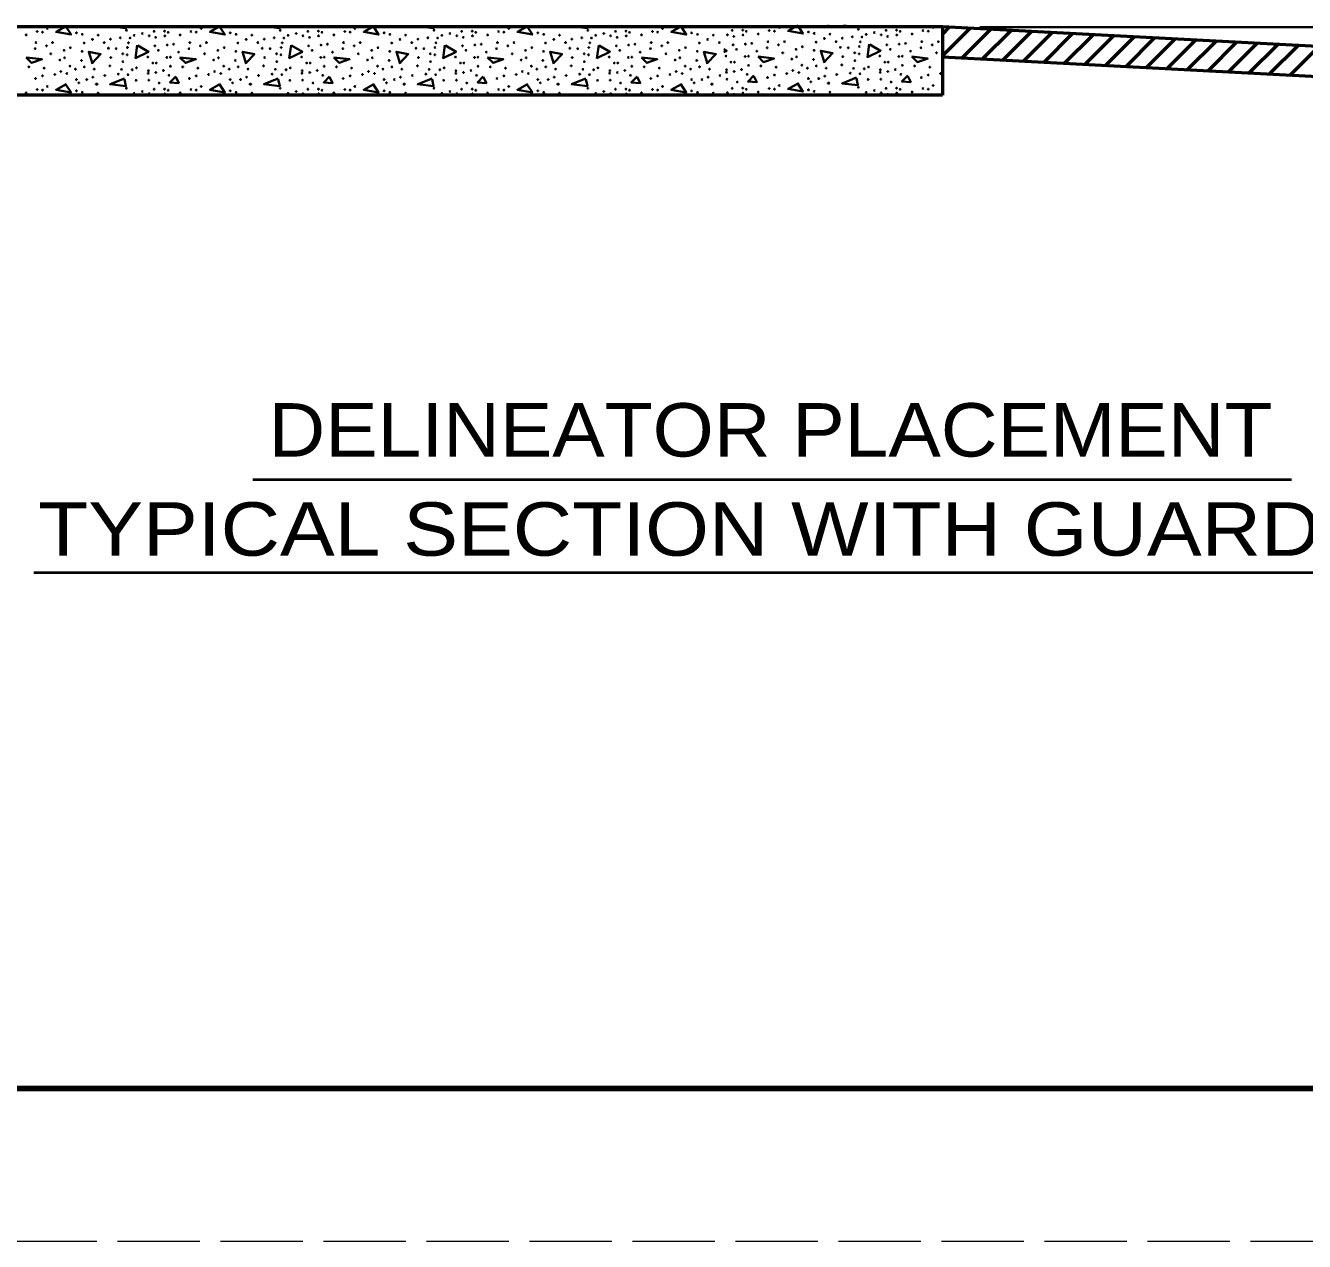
# Model space of a CAD drawing. Extents: x -54 to 626, y -41 to 399.
# Drawn here: x 33.7 to 117.5, y -41.3 to 38.4 of the extents above; entities that cross this region are included whole.
import ezdxf
from ezdxf.enums import TextEntityAlignment as Align

# ---------------------------------------------------------------- set-up
doc = ezdxf.new("R2010")
doc.units = 0
doc.header["$LTSCALE"] = 0.9
doc.linetypes.add('LONG_DASHED', pattern=[7.5, 6, -1.5])
doc.layers.add('1', color=7, linetype='Continuous', lineweight=35)
doc.layers.add('61', color=7, linetype='Continuous', lineweight=35)

msp = doc.modelspace()

# ---------------------------------------------------------------- linework, layer by layer
at = {"layer": '1', "lineweight": 53}
for p, q in [((93.8158, 38.3083), (140.6464, 35.8671)), ((93.8158, 37.7912), (94.3072, 38.2827)), ((93.8158, 36.377), (95.6514, 38.2126)), ((95.0863, 36.2332), (96.9956, 38.1425)), ((96.4301, 36.1628), (98.3397, 38.0724)), ((97.7739, 36.0924), (99.6838, 38.0024)), ((99.1177, 36.022), (101.028, 37.9323)), ((100.4615, 35.9516), (102.3722, 37.8622)), ((101.8053, 35.8812), (103.7163, 37.7922)), ((103.1491, 35.8107), (105.0604, 37.7221)), ((104.4928, 35.7403), (106.4046, 37.6521)), ((105.8366, 35.6699), (107.7488, 37.582)), ((107.1804, 35.5994), (109.0928, 37.5119)), ((108.5242, 35.529), (110.437, 37.4418)), ((109.868, 35.4586), (111.7812, 37.3717)), ((111.2117, 35.3882), (113.1253, 37.3017)), ((112.5556, 35.3177), (114.4694, 37.2317)), ((113.8993, 35.2473), (115.8136, 37.1616)), ((115.2432, 35.1769), (117.1577, 37.0915)), ((116.5869, 35.1065), (118.5019, 37.0214)), ((140.6464, 33.8456), (93.8156, 36.2998)), ((93.8158, 33.8083), (-1.1842, 33.8083))]:
    msp.add_line(p, q, dxfattribs=at)
at = {"layer": '1'}
msp.add_line((96.2767, 38.2649), (133.843, 38.2649), dxfattribs=at)
at = {"layer": '1', "lineweight": 40}
for p, q in [((48.6275, 8.6172), (116.6877, 8.6172)), ((34.2753, 2.5087), (131.065, 2.5087))]:
    msp.add_line(p, q, dxfattribs=at)
at = {"layer": '1', "lineweight": 53}
msp.add_lwpolyline([(-1.1842, 38.3083), (93.8158, 38.3083), (93.8158, 36.3054), (93.8158, 33.8083)], dxfattribs=at)
at = {"layer": '1'}
for points in [[(36.3717, 38.3083), (35.7318, 37.9592), (36.7118, 37.7792)], [(46.4517, 38.3083), (45.8118, 37.9592), (46.7918, 37.7792)], [(56.5317, 38.3083), (55.8918, 37.9592), (56.8718, 37.7792)], [(76.6917, 38.3083), (76.0518, 37.9592), (77.0318, 37.7792)], [(84.3422, 38.3702), (83.7023, 38.0212), (84.6823, 37.8412)], [(33.7718, 36.2792), (34.8118, 36.1593), (34.1318, 35.9192)], [(43.8518, 36.2792), (44.8918, 36.1593), (44.2118, 35.9192)], [(53.9318, 36.2792), (54.9718, 36.1593), (54.2918, 35.9192)], [(64.0118, 36.2792), (65.0518, 36.1593), (64.3718, 35.9192)], [(74.0918, 36.2792), (75.1318, 36.1593), (74.4518, 35.9192)], [(81.7423, 36.3412), (82.7823, 36.2212), (82.1023, 35.9812)], [(91.8223, 36.3412), (92.8623, 36.2212), (92.1823, 35.9812)]]:
    msp.add_lwpolyline(points, close=True, dxfattribs=at)
for points in [[(39.3672, 38.3083), (40.3118, 38.1992), (40.2882, 38.3083)], [(49.4472, 38.3083), (50.3918, 38.1992), (50.3682, 38.3083)], [(59.5272, 38.3083), (60.4718, 38.1992), (60.4482, 38.3083)], [(66.6117, 38.3083), (65.9718, 37.9592), (66.9518, 37.7792), (66.6118, 38.3083)], [(69.6072, 38.3083), (70.5518, 38.1992), (70.5282, 38.3083)], [(87.3377, 38.3702), (88.2823, 38.2612), (88.2587, 38.3702)], [(41.0918, 37.0592), (41.7918, 36.6593), (40.9318, 36.2392), (41.0518, 37.0793)], [(51.1718, 37.0592), (51.8718, 36.6593), (51.0118, 36.2392), (51.1318, 37.0793)], [(61.2518, 37.0592), (61.9518, 36.6593), (61.0918, 36.2392), (61.2118, 37.0793)], [(71.3318, 37.0592), (72.0318, 36.6593), (71.1718, 36.2392), (71.2918, 37.0793)], [(89.0623, 37.1212), (89.7623, 36.7212), (88.9023, 36.3012), (89.0223, 37.1412)], [(38.1118, 35.8592), (37.8718, 36.6593), (38.6518, 36.4992), (38.0918, 35.8993)], [(48.1918, 35.8592), (47.9518, 36.6593), (48.7318, 36.4992), (48.1718, 35.8993)], [(58.2718, 35.8592), (58.0318, 36.6593), (58.8118, 36.4992), (58.2518, 35.8993)], [(68.3518, 35.8592), (68.1118, 36.6593), (68.8918, 36.4992), (68.3318, 35.8993)], [(78.4318, 35.8592), (78.1918, 36.6593), (78.9718, 36.4992), (78.4118, 35.8993)], [(79.4887, 36.8318), (79.6823, 36.7212), (79.4887, 36.6266)], [(86.0823, 35.9212), (85.8423, 36.7212), (86.6223, 36.5612), (86.0623, 35.9612)], [(36.3918, 34.5192), (35.7318, 34.1593), (36.7118, 33.9793), (36.3518, 34.5392)], [(40.2118, 34.8993), (39.2718, 34.5192), (40.3118, 34.3993), (40.2118, 34.8592)], [(43.5718, 35.0392), (43.1918, 34.6392), (43.7718, 34.5992), (43.5718, 34.9992)], [(46.4718, 34.5192), (45.8118, 34.1593), (46.7918, 33.9793), (46.4318, 34.5392)], [(50.2918, 34.8993), (49.3518, 34.5192), (50.3918, 34.3993), (50.2918, 34.8592)], [(53.6518, 35.0392), (53.2718, 34.6392), (53.8518, 34.5992), (53.6518, 34.9992)], [(56.5518, 34.5192), (55.8918, 34.1593), (56.8718, 33.9793), (56.5118, 34.5392)], [(60.3718, 34.8993), (59.4318, 34.5192), (60.4718, 34.3993), (60.3718, 34.8592)], [(63.7318, 35.0392), (63.3518, 34.6392), (63.9318, 34.5992), (63.7318, 34.9992)], [(66.6318, 34.5192), (65.9718, 34.1593), (66.9518, 33.9793), (66.5918, 34.5392)], [(70.4518, 34.8993), (69.5118, 34.5192), (70.5518, 34.3993), (70.4518, 34.8592)], [(73.8118, 35.0392), (73.4318, 34.6392), (74.0118, 34.5992), (73.8118, 34.9992)], [(76.7118, 34.5192), (76.0518, 34.1593), (77.0318, 33.9793), (76.6718, 34.5392)], [(81.4623, 35.1012), (81.0823, 34.7012), (81.6623, 34.6612), (81.4623, 35.0612)], [(84.3623, 34.5812), (83.7023, 34.2212), (84.6823, 34.0412), (84.3223, 34.6012)], [(88.1823, 34.9612), (87.2423, 34.5812), (88.2823, 34.4612), (88.1823, 34.9212)], [(91.5423, 35.1012), (91.1623, 34.7012), (91.7423, 34.6612), (91.5423, 35.0612)]]:
    msp.add_lwpolyline(points, dxfattribs=at)
for centre in [(33.7796, 37.7563), (34.4953, 37.9817), (34.84, 37.942), (35.158, 38.1806), (37.0665, 37.8889), (37.4508, 37.7961), (38.4846, 37.743), (40.34, 38.0612), (40.8568, 37.7298), (41.3869, 37.8491), (41.8376, 37.7033), (42.1556, 37.995), (42.8448, 38.0082), (42.858, 37.69), (43.0778, 37.9287), (43.8596, 37.7563), (44.5753, 37.9817), (44.92, 37.942), (45.238, 38.1806), (47.1465, 37.8889), (47.5308, 37.7961), (48.5646, 37.743), (50.42, 38.0612), (50.9368, 37.7298), (51.4669, 37.8491), (51.9176, 37.7033), (52.2356, 37.995), (52.9248, 38.0082), (52.938, 37.69), (53.1578, 37.9287), (53.9396, 37.7563), (54.6553, 37.9817), (55, 37.942), (55.318, 38.1806), (57.2265, 37.8889), (57.6108, 37.7961), (58.6446, 37.743), (60.5, 38.0612), (61.0168, 37.7298), (61.5469, 37.8491), (61.9976, 37.7033), (62.3156, 37.995), (63.0048, 38.0082), (63.018, 37.69), (63.2378, 37.9287), (64.0196, 37.7563), (64.7353, 37.9817), (65.08, 37.942), (65.398, 38.1806), (67.3065, 37.8889), (67.6908, 37.7961), (68.7246, 37.743), (70.58, 38.0612), (71.0968, 37.7298), (71.6269, 37.8491), (72.0776, 37.7033), (72.3956, 37.995), (73.0848, 38.0082), (73.098, 37.69), (73.3178, 37.9287), (74.0996, 37.7563), (74.8153, 37.9817), (75.16, 37.942), (75.478, 38.1806), (77.3865, 37.8889), (77.7708, 37.7961), (78.8046, 37.743), (79.7281, 37.7652), (80.0461, 38.0569), (80.7353, 38.0702), (80.7485, 37.752), (80.9683, 37.9906), (81.7501, 37.8182), (82.4658, 38.0436), (82.8105, 38.0039), (83.1285, 38.2425), (85.037, 37.9508), (85.4213, 37.8581), (86.4551, 37.805), (88.3105, 38.1232), (88.8273, 37.7917), (89.3574, 37.9111), (89.8081, 37.7652), (90.1261, 38.0569), (90.8153, 38.0702), (90.8285, 37.752), (91.0483, 37.9906), (91.8301, 37.8182), (92.5458, 38.0436), (92.8905, 38.0039), (93.2085, 38.2425), (34.3629, 36.8548), (34.4158, 37.2526), (35.105, 37.0405), (35.5026, 37.2526), (36.6688, 36.9211), (37.5701, 37.226), (38.1135, 37.4647), (38.8821, 37.2526), (39.1604, 36.8814), (39.293, 37.4779), (39.6773, 36.8548), (39.9424, 37.5708), (40.4062, 36.9344), (40.4725, 37.2393), (40.5785, 37.5575), (42.2086, 37.0405), (42.2617, 37.5972), (43.0171, 37.0935), (43.4355, 37.1465), (44.4429, 36.8548), (44.4958, 37.2526), (45.185, 37.0405), (45.5826, 37.2526), (46.7488, 36.9211), (47.6501, 37.226), (48.1935, 37.4647), (48.9621, 37.2526), (49.2404, 36.8814), (49.373, 37.4779), (49.7573, 36.8548), (50.0224, 37.5708), (50.4862, 36.9344), (50.5525, 37.2393), (50.6585, 37.5575), (52.2886, 37.0405), (52.3417, 37.5972), (53.0971, 37.0935), (53.5155, 37.1465), (54.5229, 36.8548), (54.5758, 37.2526), (55.265, 37.0405), (55.6626, 37.2526), (56.8288, 36.9211), (57.7301, 37.226), (58.2735, 37.4647), (59.0421, 37.2526), (59.3204, 36.8814), (59.453, 37.4779), (59.8373, 36.8548), (60.1024, 37.5708), (60.5662, 36.9344), (60.6325, 37.2393), (60.7385, 37.5575), (62.3686, 37.0405), (62.4217, 37.5972), (63.1771, 37.0935), (63.5955, 37.1465), (64.6029, 36.8548), (64.6558, 37.2526), (65.345, 37.0405), (65.7426, 37.2526), (66.9088, 36.9211), (67.8101, 37.226), (68.3535, 37.4647), (69.1221, 37.2526), (69.4004, 36.8814), (69.533, 37.4779), (69.9173, 36.8548), (70.1824, 37.5708), (70.6462, 36.9344), (70.7125, 37.2393), (70.8185, 37.5575), (72.4486, 37.0405), (72.5017, 37.5972), (73.2571, 37.0935), (73.6755, 37.1465), (74.6829, 36.8548), (74.7358, 37.2526), (75.425, 37.0405), (75.8226, 37.2526), (76.9888, 36.9211), (77.8901, 37.226), (78.4335, 37.4647), (79.2021, 37.2526), (80.0991, 37.1024), (80.1522, 37.6591), (80.9076, 37.1554), (81.326, 37.2084), (82.3334, 36.9167), (82.3863, 37.3145), (83.0755, 37.1024), (83.4731, 37.3145), (84.6393, 36.983), (85.5406, 37.2879), (86.084, 37.5266), (86.8526, 37.3145), (87.1309, 36.9433), (87.2635, 37.5399), (87.6478, 36.9167), (87.9129, 37.6327), (88.3767, 36.9963), (88.443, 37.3012), (88.549, 37.6194), (90.1791, 37.1024), (90.2322, 37.6591), (90.9876, 37.1554), (91.406, 37.2084), (92.4134, 36.9167), (92.4663, 37.3145), (93.1555, 37.1024), (93.5531, 37.3145), (35.3833, 36.5234), (35.9797, 36.1124), (36.258, 36.7487), (36.2978, 36.2583), (37.3978, 36.0859), (37.4375, 36.6825), (39.3194, 36.2715), (40.1014, 36.5234), (40.393, 36.4571), (41.7448, 36.3113), (42.434, 36.7487), (42.9974, 36.2825), (43.2235, 36.2981), (43.7669, 36.6295), (45.4633, 36.5234), (46.0597, 36.1124), (46.338, 36.7487), (46.3778, 36.2583), (47.4778, 36.0859), (47.5175, 36.6825), (49.3994, 36.2715), (50.1814, 36.5234), (50.473, 36.4571), (51.8248, 36.3113), (52.514, 36.7487), (53.0774, 36.2825), (53.3035, 36.2981), (53.8469, 36.6295), (55.5433, 36.5234), (56.1397, 36.1124), (56.418, 36.7487), (56.4578, 36.2583), (57.5578, 36.0859), (57.5975, 36.6825), (59.4794, 36.2715), (60.2614, 36.5234), (60.553, 36.4571), (61.9048, 36.3113), (62.594, 36.7487), (63.1574, 36.2825), (63.3835, 36.2981), (63.9269, 36.6295), (65.6233, 36.5234), (66.2197, 36.1124), (66.498, 36.7487), (66.5378, 36.2583), (67.6378, 36.0859), (67.6775, 36.6825), (69.5594, 36.2715), (70.3414, 36.5234), (70.633, 36.4571), (71.9848, 36.3113), (72.674, 36.7487), (73.2374, 36.2825), (73.4635, 36.2981), (74.0069, 36.6295), (75.7033, 36.5234), (76.2997, 36.1124), (76.578, 36.7487), (76.6178, 36.2583), (77.7178, 36.0859), (77.7575, 36.6825), (79.6353, 36.3732), (80.3245, 36.8107), (80.8879, 36.3445), (81.114, 36.36), (81.6574, 36.6914), (83.3538, 36.5853), (83.9502, 36.1744), (84.2285, 36.8107), (84.2683, 36.3202), (85.3683, 36.1478), (85.408, 36.7444), (87.2899, 36.3335), (88.0719, 36.5853), (88.0852, 36.0683), (88.3635, 36.519), (89.7153, 36.3732), (90.4045, 36.8107), (90.9679, 36.3445), (91.194, 36.36), (91.7374, 36.6914), (93.4338, 36.5853), (33.952, 35.6617), (34.946, 35.5821), (36.046, 35.3568), (36.4435, 35.229), (36.6424, 35.7147), (37.0002, 35.5158), (37.5833, 35.6617), (38.2327, 35.5158), (39.2532, 35.728), (39.8098, 35.1893), (40.0219, 35.5026), (40.1147, 36.0063), (40.7243, 35.4761), (41.0026, 35.5953), (41.7713, 35.2423), (41.7846, 35.4098), (42.0762, 35.9135), (42.2749, 35.2953), (42.3014, 35.9135), (42.7653, 35.4231), (43.2235, 35.7014), (44.032, 35.6617), (45.026, 35.5821), (46.126, 35.3568), (46.5235, 35.229), (46.7224, 35.7147), (47.0802, 35.5158), (47.6633, 35.6617), (48.3127, 35.5158), (49.3332, 35.728), (49.8898, 35.1893), (50.1019, 35.5026), (50.1947, 36.0063), (50.8043, 35.4761), (51.0826, 35.5953), (51.8513, 35.2423), (51.8646, 35.4098), (52.1562, 35.9135), (52.3549, 35.2953), (52.3814, 35.9135), (52.8453, 35.4231), (53.3035, 35.7014), (54.112, 35.6617), (55.106, 35.5821), (56.206, 35.3568), (56.6035, 35.229), (56.8024, 35.7147), (57.1602, 35.5158), (57.7433, 35.6617), (58.3927, 35.5158), (59.4132, 35.728), (59.9698, 35.1893), (60.1819, 35.5026), (60.2747, 36.0063), (60.8843, 35.4761), (61.1626, 35.5953), (61.9313, 35.2423), (61.9446, 35.4098), (62.2362, 35.9135), (62.4349, 35.2953), (62.4614, 35.9135), (62.9253, 35.4231), (63.3835, 35.7014), (64.192, 35.6617), (65.186, 35.5821), (66.286, 35.3568), (66.6835, 35.229), (66.8824, 35.7147), (67.2402, 35.5158), (67.8233, 35.6617), (68.4727, 35.5158), (69.4932, 35.728), (70.0498, 35.1893), (70.2619, 35.5026), (70.3547, 36.0063), (70.9643, 35.4761), (71.2426, 35.5953), (72.0113, 35.2423), (72.0246, 35.4098), (72.3162, 35.9135), (72.5149, 35.2953), (72.5414, 35.9135), (73.0053, 35.4231), (73.4635, 35.7014), (74.272, 35.6617), (75.266, 35.5821), (76.366, 35.3568), (76.7635, 35.229), (76.9624, 35.7147), (77.3202, 35.5158), (77.9033, 35.6617), (78.5527, 35.5158), (79.6618, 35.3042), (79.6751, 35.4717), (79.9667, 35.9754), (80.1654, 35.3572), (80.1919, 35.9754), (80.6558, 35.485), (81.114, 35.7633), (81.9225, 35.7236), (82.9165, 35.6441), (83.6189, 35.2246), (84.0165, 35.4187), (84.414, 35.2909), (84.6129, 35.7766), (84.9707, 35.5777), (85.5538, 35.7236), (86.2032, 35.5777), (87.2237, 35.7899), (87.7803, 35.2512), (87.9924, 35.5645), (88.4165, 35.2114), (88.6948, 35.538), (88.9731, 35.6573), (89.7418, 35.3042), (89.7551, 35.4717), (90.0467, 35.9754), (90.2454, 35.3572), (90.2719, 35.9754), (90.7358, 35.485), (91.194, 35.7633), (92.0025, 35.7236), (92.9965, 35.6441), (93.6989, 35.2246), (34.3893, 34.8976), (34.84, 35.0699), (35.158, 34.3806), (35.6484, 35.1627), (37.0664, 34.8313), (37.2255, 34.6192), (37.7423, 34.8313), (38.14, 34.9904), (38.3653, 34.5264), (38.4183, 34.5264), (38.9219, 35.0964), (40.446, 35.1495), (40.9761, 34.7783), (41.811, 34.7915), (42.487, 34.606), (43.1308, 35.1097), (44.4693, 34.8976), (44.92, 35.0699), (45.238, 34.3806), (45.7284, 35.1627), (47.1464, 34.8313), (47.3055, 34.6192), (47.8223, 34.8313), (48.22, 34.9904), (48.4453, 34.5264), (48.4983, 34.5264), (49.0019, 35.0964), (50.526, 35.1495), (51.0561, 34.7783), (51.891, 34.7915), (52.567, 34.606), (53.2108, 35.1097), (54.5493, 34.8976), (55, 35.0699), (55.318, 34.3806), (55.8084, 35.1627), (57.2264, 34.8313), (57.3855, 34.6192), (57.9023, 34.8313), (58.3, 34.9904), (58.5253, 34.5264), (58.5783, 34.5264), (59.0819, 35.0964), (60.606, 35.1495), (61.1361, 34.7783), (61.971, 34.7915), (62.647, 34.606), (63.2908, 35.1097), (64.6293, 34.8976), (65.08, 35.0699), (65.398, 34.3806), (65.8884, 35.1627), (67.3064, 34.8313), (67.4655, 34.6192), (67.9823, 34.8313), (68.38, 34.9904), (68.6053, 34.5264), (68.6583, 34.5264), (69.1619, 35.0964), (70.686, 35.1495), (71.2161, 34.7783), (72.051, 34.7915), (72.727, 34.606), (73.3708, 35.1097), (74.7093, 34.8976), (75.16, 35.0699), (75.478, 34.3806), (75.9684, 35.1627), (77.3864, 34.8313), (77.5455, 34.6192), (78.0623, 34.8313), (78.46, 34.9904), (78.6853, 34.5264), (78.7383, 34.5264), (79.2419, 35.0964), (79.7015, 34.8534), (80.3775, 34.6679), (81.0213, 35.1716), (82.3598, 34.9595), (82.8105, 35.1318), (83.1285, 34.4425), (85.0369, 34.8933), (85.196, 34.6811), (85.7128, 34.8933), (86.1105, 35.0524), (86.3358, 34.5883), (86.3888, 34.5883), (86.8924, 35.1584), (88.9466, 34.8402), (89.7815, 34.8534), (90.4575, 34.6679), (91.1013, 35.1716), (92.4398, 34.9595), (92.8905, 35.1318), (93.2085, 34.4425), (33.7796, 33.9563), (34.4953, 34.1817), (34.84, 34.142), (37.0665, 34.0889), (37.4508, 33.9961), (38.4846, 33.943), (40.34, 34.2612), (40.8568, 33.9298), (41.3869, 34.0491), (41.8376, 33.9033), (42.1556, 34.195), (42.8448, 34.2082), (42.858, 33.89), (43.0778, 34.1287), (43.8596, 33.9563), (44.5753, 34.1817), (44.92, 34.142), (47.1465, 34.0889), (47.5308, 33.9961), (48.5646, 33.943), (50.42, 34.2612), (50.9368, 33.9298), (51.4669, 34.0491), (51.9176, 33.9033), (52.2356, 34.195), (52.9248, 34.2082), (52.938, 33.89), (53.1578, 34.1287), (53.9396, 33.9563), (54.6553, 34.1817), (55, 34.142), (57.2265, 34.0889), (57.6108, 33.9961), (58.6446, 33.943), (60.5, 34.2612), (61.0168, 33.9298), (61.5469, 34.0491), (61.9976, 33.9033), (62.3156, 34.195), (63.0048, 34.2082), (63.018, 33.89), (63.2378, 34.1287), (64.0196, 33.9563), (64.7353, 34.1817), (65.08, 34.142), (67.3065, 34.0889), (67.6908, 33.9961), (68.7246, 33.943), (70.58, 34.2612), (71.0968, 33.9298), (71.6269, 34.0491), (72.0776, 33.9033), (72.3956, 34.195), (73.0848, 34.2082), (73.098, 33.89), (73.3178, 34.1287), (74.0996, 33.9563), (74.8153, 34.1817), (75.16, 34.142), (77.3865, 34.0889), (77.7708, 33.9961), (78.8046, 33.943), (79.7281, 33.9652), (80.0461, 34.2569), (80.7353, 34.2702), (80.7485, 33.952), (80.9683, 34.1906), (81.7501, 34.0182), (82.4658, 34.2436), (82.8105, 34.2039), (85.037, 34.1508), (85.4213, 34.0581), (86.4551, 34.005), (88.3105, 34.3232), (88.8273, 33.9917), (89.3574, 34.1111), (89.8081, 33.9652), (90.1261, 34.2569), (90.8153, 34.2702), (90.8285, 33.952), (91.0483, 34.1906), (91.8301, 34.0182), (92.5458, 34.2436), (92.8905, 34.2039)]:
    msp.add_circle(centre, 0.0265, dxfattribs=at)
for centre, start, end in [((38.3653, 38.3264), 223.38683, 316.61317), ((38.4183, 38.3264), 223.38683, 316.61317), ((48.4453, 38.3264), 223.38683, 316.61317), ((48.4983, 38.3264), 223.38683, 316.61317), ((58.5253, 38.3264), 223.38683, 316.61317), ((58.5783, 38.3264), 223.38683, 316.61317), ((68.6053, 38.3264), 223.38683, 316.61317), ((68.6583, 38.3264), 223.38683, 316.61317), ((78.6853, 38.3264), 223.38683, 316.61317), ((78.7383, 38.3264), 223.38683, 316.61317), ((86.3358, 38.3883), 223.38683, 316.61317), ((86.3888, 38.3883), 223.38683, 316.61317), ((42.2617, 33.7972), 24.63166, 155.36834), ((52.3417, 33.7972), 24.63166, 155.36834), ((62.4217, 33.7972), 24.63166, 155.36834), ((72.5017, 33.7972), 24.63166, 155.36834), ((80.1522, 33.8591), 24.63166, 155.36834), ((90.2322, 33.8591), 24.63166, 155.36834)]:
    msp.add_arc(centre, 0.0265, start, end, dxfattribs=at)
at = {"layer": '61', "lineweight": 158}
msp.add_line((614.7178, -31.3361), (-24.3422, -31.3161), dxfattribs=at)
at = {"layer": '61', "linetype": 'LONG_DASHED', "lineweight": 13}
msp.add_line((625.6577, -41.3161), (-54.4022, -41.3361), dxfattribs=at)

# ---------------------------------------------------------------- texts
at = {"layer": '1'}
for s, width, p in [('DELINEATOR PLACEMENT', 1.1, (82.5526, 10.1172)), ('TYPICAL SECTION WITH GUARDRAIL', 1.15, (82.5526, 3.6172))]:
    msp.add_text(s, height=3.5, dxfattribs=dict(at, width=width)).set_placement(p, align=Align.CENTER)

doc.saveas('drawing.dxf')
